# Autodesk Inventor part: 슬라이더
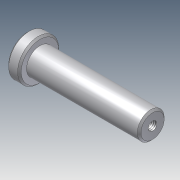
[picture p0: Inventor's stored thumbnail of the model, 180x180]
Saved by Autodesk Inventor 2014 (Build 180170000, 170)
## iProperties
Created: 2011-04
Part Number: 슬라이더
Document SubType Name: Modeling
Designer: 한국산업디자인학원 [http://gmhk.co.kr]
Density: 1 g/cm^3
Material: 일반
Appearance: 기본값
Author: pww
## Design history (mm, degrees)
sketch "스케치1"
  geometry: L1 (-7, 0)-(63, 0); L2 (63, 0)-(63, 7.5); L3 (63, 7.5)-(0, 7.5); L4 (-7, 0)-(-7, 11.5); L5 (-7, 11.5)-(0, 11.5); L6 (0, 11.5)-(0, 7.5); 1 further point
  constraints: 12 end point, 3 perpendicular, 2 horizontal, 2 point on line, 1 parallel
  dimensions: "d1" = 70 distance of L1.start L1.end; "d19" = 15 diameter of L3 L1; "d20" = 7 distance of L4.end L5.end; "d21" = 23 diameter of L5 L1
revolve "회전1" stored, may be unused: angle "d4" = 90 deg
chamfer "모따기1" distance "d16" = 1; stored, may be unused: second distance "d17" = 2, angle "d18" = 45 deg
hole "구멍2" diameter "d24" = 4.917; stored, may be unused: countersink angle "d28" = 90 deg, drill point angle "d30" = 118 deg; dims "d22" = 10, "d23" = 10, "d25" = 10, "d26" = 4, "d27" = 2, "d29" = 13
node "솔리드1"
